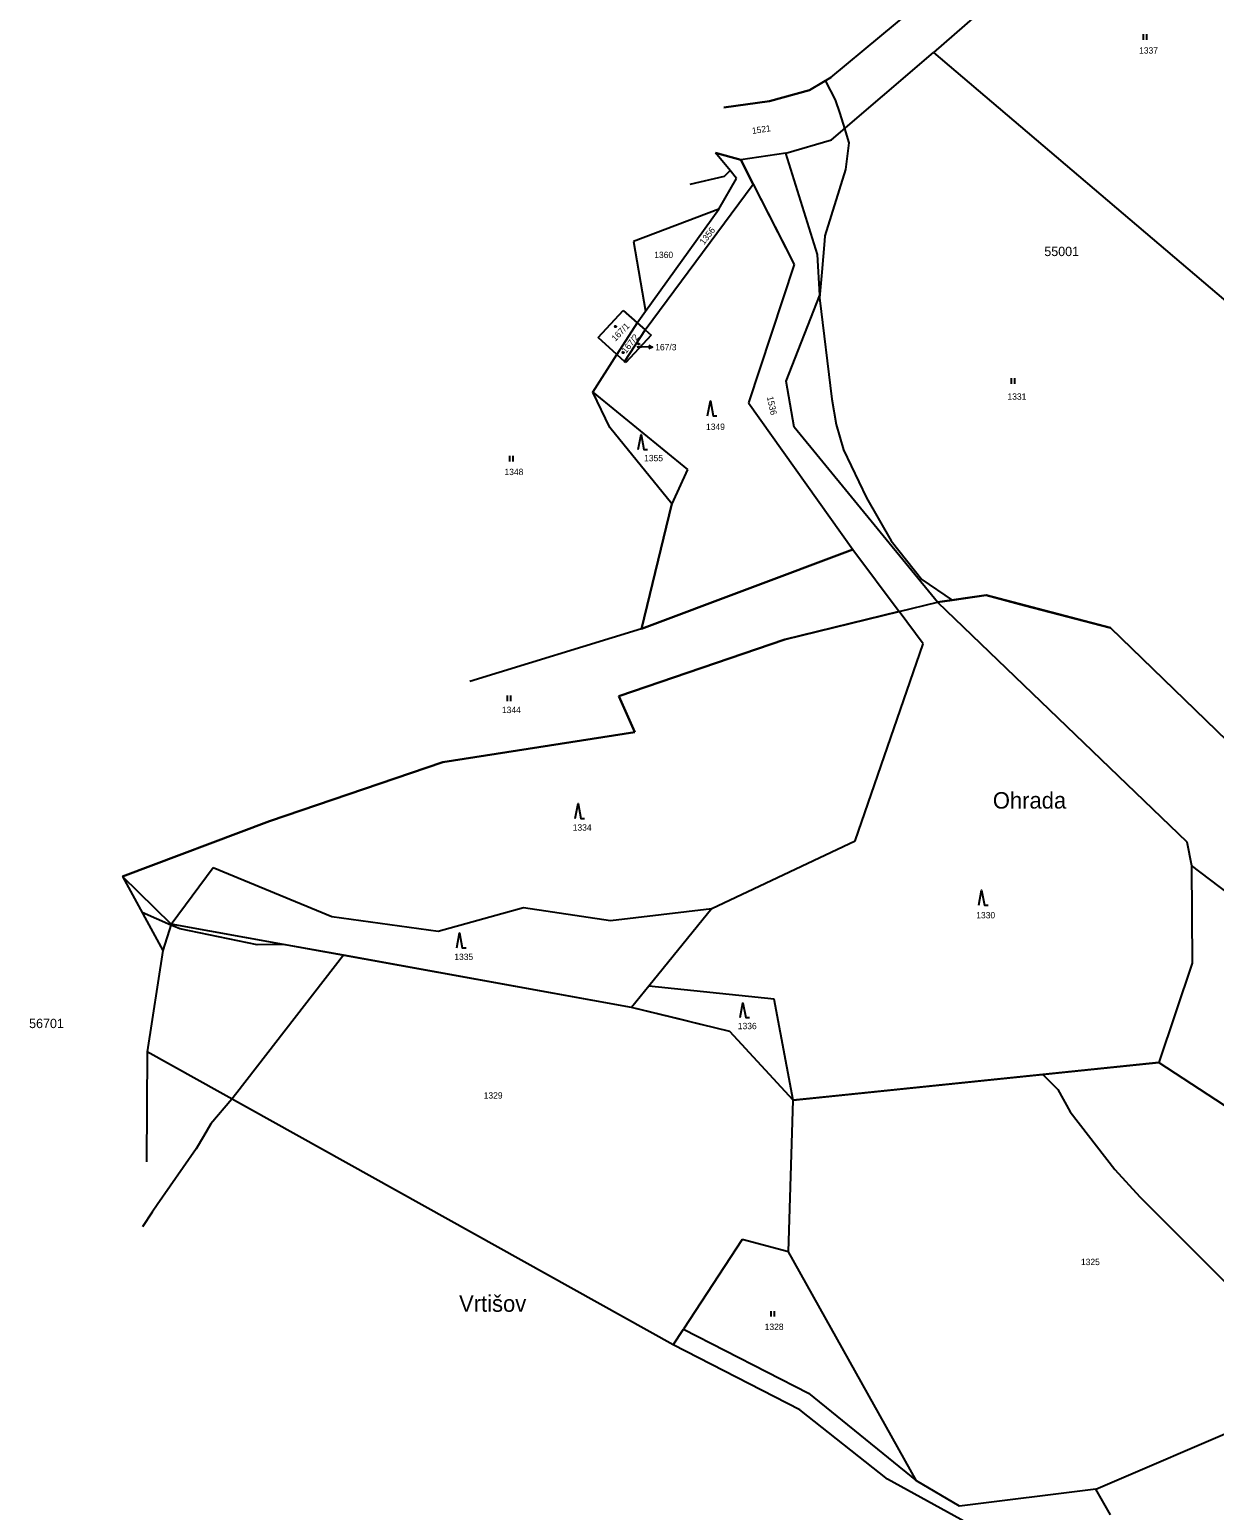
# Model space of a CAD drawing. Extents: x -792913 to -792113, y -1112764 to -1111548.
# Drawn here: x -792913.1 to -792595.9, y -1112340 to -1111943.5 of the extents above; entities that cross this region are included whole.
import ezdxf

# ---------------------------------------------------------------- set-up
doc = ezdxf.new("R2010")
doc.units = 0
for name, color, linetype in [('Vrstva 1', 7, 'Continuous'), ('Vrstva 11', 7, 'Continuous'), ('Vrstva 12', 7, 'Continuous'), ('Vrstva 2', 7, 'Continuous'), ('Vrstva 3', 7, 'Continuous'), ('Vrstva 5', 7, 'Continuous'), ('Vrstva 7', 7, 'Continuous')]:
    doc.layers.add(name, color=color, linetype=linetype)

msp = doc.modelspace()

# ---------------------------------------------------------------- linework, layer by layer
at = {"layer": 'Vrstva 1'}
for p, q in [((-792698.63, -1111956.28), (-792632.44, -1111901.27)), ((-792613.34, -1111899), (-792671.11, -1111949.58)), ((-792698.44, -1111972.97), (-792671.11, -1111949.58)), ((-792671.11, -1111949.58), (-792589.25, -1112019.19)), ((-792698.63, -1111956.28), (-792704.33, -1111959.64)), ((-792704.33, -1111959.64), (-792715.05, -1111962.61)), ((-792715.05, -1111962.61), (-792727.23, -1111964.35)), ((-792710.66, -1111976.53), (-792698.44, -1111972.97)), ((-792722.71, -1111978.37), (-792729.43, -1111976.43)), ((-792729.43, -1111976.43), (-792729.43, -1111976.43)), ((-792725.54, -1111981.2), (-792729.43, -1111976.43)), ((-792710.66, -1111976.53), (-792722.71, -1111978.37)), ((-792702.13, -1112003.67), (-792710.66, -1111976.53)), ((-792727.08, -1111982.75), (-792725.54, -1111981.2)), ((-792723.81, -1111983.32), (-792725.54, -1111981.2)), ((-792719.38, -1111984.88), (-792722.71, -1111978.37)), ((-792748.29, -1112023.9), (-792719.38, -1111984.88)), ((-792736.25, -1111984.83), (-792727.08, -1111982.75)), ((-792728.56, -1111991.52), (-792723.81, -1111983.32)), ((-792719.38, -1111984.88), (-792708.39, -1112006.35)), ((-792728.56, -1111991.52), (-792751.41, -1112000.24)), ((-792748.18, -1112018.91), (-792728.56, -1111991.52)), ((-792751.41, -1112000.24), (-792748.18, -1112018.91)), ((-792701.57, -1112014.57), (-792702.13, -1112003.67)), ((-792708.39, -1112006.35), (-792720.64, -1112043.39)), ((-792710.57, -1112037.62), (-792701.57, -1112014.57)), ((-792760.89, -1112025.9), (-792754.15, -1112018.68)), ((-792754.15, -1112018.68), (-792754.15, -1112018.68)), ((-792754.15, -1112018.68), (-792750.41, -1112022.02)), ((-792750.41, -1112022.02), (-792748.18, -1112018.91)), ((-792750.41, -1112022.02), (-792755.88, -1112030.47)), ((-792748.29, -1112023.9), (-792753.83, -1112032.34)), ((-792750.41, -1112022.02), (-792748.29, -1112023.9)), ((-792748.29, -1112023.9), (-792746.73, -1112025.29)), ((-792755.88, -1112030.47), (-792760.89, -1112025.9)), ((-792746.73, -1112025.29), (-792753.49, -1112032.65)), ((-792762.35, -1112040.52), (-792755.88, -1112030.47)), ((-792755.88, -1112030.47), (-792753.83, -1112032.34)), ((-792753.49, -1112032.65), (-792753.83, -1112032.34)), ((-792762.35, -1112040.52), (-792736.94, -1112061.27)), ((-792757.8, -1112049.99), (-792762.35, -1112040.52)), ((-792762.35, -1112040.52), (-792762.35, -1112040.52)), ((-792708.41, -1112049.93), (-792710.57, -1112037.62)), ((-792720.64, -1112043.39), (-792692.69, -1112082.72)), ((-792741.17, -1112070.46), (-792757.8, -1112049.99)), ((-792670.05, -1112096.82), (-792708.41, -1112049.93)), ((-792736.94, -1112061.27), (-792741.17, -1112070.46)), ((-792741.17, -1112070.46), (-792749.31, -1112103.9)), ((-792749.31, -1112103.9), (-792692.69, -1112082.72)), ((-792692.69, -1112082.72), (-792680.31, -1112099.32)), ((-792657.05, -1112094.97), (-792670.05, -1112096.82)), ((-792623.73, -1112103.69), (-792657.05, -1112094.97)), ((-792680.31, -1112099.32), (-792710.95, -1112106.79)), ((-792680.31, -1112099.32), (-792670.05, -1112096.82)), ((-792673.9, -1112107.92), (-792680.31, -1112099.32)), ((-792670.05, -1112096.82), (-792603.33, -1112161)), ((-792749.31, -1112103.9), (-792795.23, -1112118.08)), ((-792583.87, -1112142.36), (-792623.73, -1112103.69)), ((-792710.95, -1112106.79), (-792755.33, -1112121.94)), ((-792692.04, -1112160.72), (-792673.9, -1112107.92)), ((-792795.23, -1112118.08), (-792795.23, -1112118.08)), ((-792795.23, -1112118.08), (-792795.23, -1112118.08)), ((-792755.33, -1112121.94), (-792751.11, -1112131.6)), ((-792751.11, -1112131.6), (-792802.48, -1112139.62)), ((-792802.48, -1112139.62), (-792848.89, -1112155.49)), ((-792848.89, -1112155.49), (-792888.23, -1112170.24)), ((-792730.46, -1112178.86), (-792692.04, -1112160.72)), ((-792603.33, -1112161), (-792602.02, -1112167.3)), ((-792875.18, -1112183.03), (-792863.98, -1112167.89)), ((-792863.98, -1112167.89), (-792832.19, -1112181)), ((-792504.64, -1112241.47), (-792602.02, -1112167.3)), ((-792602.02, -1112167.3), (-792601.83, -1112193.48)), ((-792888.23, -1112170.24), (-792888.23, -1112170.24)), ((-792888.23, -1112170.24), (-792877.43, -1112190.06)), ((-792803.74, -1112184.93), (-792780.88, -1112178.61)), ((-792780.88, -1112178.61), (-792757.6, -1112182.07)), ((-792757.6, -1112182.07), (-792730.46, -1112178.86)), ((-792730.46, -1112178.86), (-792747.34, -1112199.64)), ((-792875.18, -1112183.03), (-792877.43, -1112190.06)), ((-792751.95, -1112205.32), (-792875.18, -1112183.03)), ((-792832.19, -1112181), (-792803.74, -1112184.93)), ((-792877.43, -1112190.06), (-792881.63, -1112217.24)), ((-792601.83, -1112193.48), (-792610.82, -1112220.07)), ((-792747.34, -1112199.64), (-792751.95, -1112205.32)), ((-792713.76, -1112203.08), (-792747.34, -1112199.64)), ((-792708.65, -1112230.19), (-792713.76, -1112203.08)), ((-792725.6, -1112211.79), (-792751.95, -1112205.32)), ((-792708.65, -1112230.19), (-792725.6, -1112211.79)), ((-792881.63, -1112217.24), (-792881.75, -1112246.69)), ((-792740.8, -1112295.69), (-792881.63, -1112217.24)), ((-792708.65, -1112230.19), (-792610.82, -1112220.07)), ((-792610.82, -1112220.07), (-792534.68, -1112269.92)), ((-792709.94, -1112270.78), (-792708.65, -1112230.19)), ((-792722.34, -1112267.5), (-792738.05, -1112291.49)), ((-792709.94, -1112270.78), (-792722.34, -1112267.5)), ((-792675.67, -1112332.12), (-792709.94, -1112270.78)), ((-792740.8, -1112295.69), (-792738.05, -1112291.49)), ((-792738.05, -1112291.49), (-792704.62, -1112308.67)), ((-792706.91, -1112313.12), (-792740.8, -1112295.69)), ((-792704.62, -1112308.67), (-792675.67, -1112332.12)), ((-792683.47, -1112331.71), (-792706.91, -1112313.12)), ((-792627.65, -1112334.38), (-792582.04, -1112314.76)), ((-792662.04, -1112343.48), (-792683.47, -1112331.71)), ((-792664.12, -1112338.86), (-792675.67, -1112332.12)), ((-792627.65, -1112334.38), (-792664.12, -1112338.86)), ((-792623.71, -1112341.2), (-792627.65, -1112334.38))]:
    msp.add_line(p, q, dxfattribs=at)
at = {"layer": 'Vrstva 11'}
for p, q in [((-792698.63, -1111956.28), (-792632.44, -1111901.27)), ((-792704.33, -1111959.64), (-792700.12, -1111957.16)), ((-792700.12, -1111957.16), (-792698.63, -1111956.28)), ((-792700.12, -1111957.16), (-792700.05, -1111957.28)), ((-792700.05, -1111957.28), (-792697.42, -1111962.27)), ((-792715.05, -1111962.61), (-792704.33, -1111959.64)), ((-792727.23, -1111964.35), (-792715.05, -1111962.61)), ((-792697.42, -1111962.27), (-792696.23, -1111965.97)), ((-792696.23, -1111965.97), (-792694.95, -1111969.98)), ((-792694.95, -1111969.98), (-792693.74, -1111973.75)), ((-792729.43, -1111976.43), (-792722.71, -1111978.37)), ((-792693.74, -1111973.75), (-792694.67, -1111980.93)), ((-792722.71, -1111978.37), (-792719.38, -1111984.88)), ((-792694.67, -1111980.93), (-792700.19, -1111998.72)), ((-792719.38, -1111984.88), (-792711.64, -1112000)), ((-792711.64, -1112000), (-792708.39, -1112006.35)), ((-792700.3, -1112000), (-792701.01, -1112008.42)), ((-792700.19, -1111998.72), (-792700.3, -1112000)), ((-792708.39, -1112006.35), (-792720.64, -1112043.39)), ((-792701.01, -1112008.42), (-792701.59, -1112015.27)), ((-792701.59, -1112015.27), (-792698.3, -1112042.41)), ((-792757.8, -1112049.99), (-792762.35, -1112040.52)), ((-792720.64, -1112043.39), (-792692.69, -1112082.72)), ((-792698.3, -1112042.41), (-792697.16, -1112049.21)), ((-792741.17, -1112070.46), (-792757.8, -1112049.99)), ((-792697.16, -1112049.21), (-792695.17, -1112056.02)), ((-792695.17, -1112056.02), (-792689.05, -1112068.84)), ((-792749.31, -1112103.9), (-792741.17, -1112070.46)), ((-792689.05, -1112068.84), (-792682.49, -1112080.4)), ((-792682.49, -1112080.4), (-792674.2, -1112090.73)), ((-792692.69, -1112082.72), (-792749.31, -1112103.9)), ((-792674.2, -1112090.73), (-792666.1, -1112096.26)), ((-792670.05, -1112096.82), (-792666.1, -1112096.26)), ((-792666.1, -1112096.26), (-792657.05, -1112094.97)), ((-792657.05, -1112094.97), (-792646.75, -1112097.66)), ((-792710.95, -1112106.79), (-792680.31, -1112099.32)), ((-792680.31, -1112099.32), (-792670.05, -1112096.82)), ((-792646.75, -1112097.66), (-792623.73, -1112103.69)), ((-792623.73, -1112103.69), (-792583.87, -1112142.36)), ((-792755.33, -1112121.94), (-792710.95, -1112106.79)), ((-792751.11, -1112131.6), (-792755.33, -1112121.94)), ((-792802.48, -1112139.62), (-792751.11, -1112131.6)), ((-792848.89, -1112155.49), (-792802.48, -1112139.62)), ((-792888.23, -1112170.24), (-792848.89, -1112155.49)), ((-792589.1, -1112177.14), (-792602.02, -1112167.3)), ((-792602.02, -1112167.3), (-792601.83, -1112193.48)), ((-792875.18, -1112183.03), (-792888.23, -1112170.24)), ((-792875.26, -1112183.27), (-792882.98, -1112179.87)), ((-792874.55, -1112183.58), (-792875.26, -1112183.27)), ((-792845.09, -1112188.48), (-792875.18, -1112183.03)), ((-792872.85, -1112184.33), (-792874.55, -1112183.58)), ((-792852.15, -1112188.56), (-792872.85, -1112184.33)), ((-792829.1, -1112191.37), (-792857.58, -1112228.22)), ((-792845.09, -1112188.48), (-792852.15, -1112188.56)), ((-792829.1, -1112191.37), (-792845.09, -1112188.48)), ((-792751.95, -1112205.32), (-792829.1, -1112191.37)), ((-792601.83, -1112193.48), (-792610.82, -1112220.07)), ((-792739, -1112208.5), (-792751.95, -1112205.32)), ((-792733.39, -1112209.87), (-792739, -1112208.5)), ((-792733.33, -1112209.89), (-792733.39, -1112209.87)), ((-792725.6, -1112211.79), (-792733.33, -1112209.89)), ((-792708.65, -1112230.19), (-792725.6, -1112211.79)), ((-792641.89, -1112223.28), (-792703.35, -1112229.64)), ((-792610.82, -1112220.07), (-792641.89, -1112223.28)), ((-792641.89, -1112223.28), (-792637.81, -1112227.3)), ((-792637.81, -1112227.3), (-792634.53, -1112233.29)), ((-792858.96, -1112229.87), (-792864.53, -1112236.54)), ((-792857.58, -1112228.22), (-792858.96, -1112229.87)), ((-792703.35, -1112229.64), (-792708.65, -1112230.19)), ((-792634.53, -1112233.29), (-792622.53, -1112248.77)), ((-792864.53, -1112236.54), (-792866.5, -1112239.88)), ((-792868.47, -1112243.23), (-792878.94, -1112258.24)), ((-792866.5, -1112239.88), (-792868.47, -1112243.23)), ((-792622.53, -1112248.77), (-792615.88, -1112256.1)), ((-792878.94, -1112258.24), (-792880.24, -1112260.17)), ((-792615.88, -1112256.1), (-792581.75, -1112290.24)), ((-792880.24, -1112260.17), (-792882.88, -1112264.08))]:
    msp.add_line(p, q, dxfattribs=at)
at = {"layer": 'Vrstva 12'}
for p, q in [((-792760.89, -1112025.9), (-792754.15, -1112018.68)), ((-792754.15, -1112018.68), (-792750.41, -1112022.02)), ((-792750.41, -1112022.02), (-792748.29, -1112023.9)), ((-792748.29, -1112023.9), (-792746.73, -1112025.29)), ((-792755.88, -1112030.47), (-792760.89, -1112025.9)), ((-792746.73, -1112025.29), (-792753.49, -1112032.65)), ((-792755.88, -1112030.47), (-792753.83, -1112032.34)), ((-792753.49, -1112032.65), (-792753.83, -1112032.34))]:
    msp.add_line(p, q, dxfattribs=at)
at = {"layer": 'Vrstva 3'}
for p, q in [((-792615, -1111944.73), (-792615, -1111946.23)), ((-792614, -1111946.23), (-792614, -1111944.73)), ((-792650.31, -1112036.83), (-792650.31, -1112038.33)), ((-792649.31, -1112038.33), (-792649.31, -1112036.83)), ((-792784.65, -1112057.62), (-792784.65, -1112059.12)), ((-792783.65, -1112059.12), (-792783.65, -1112057.62)), ((-792785.24, -1112121.81), (-792785.24, -1112123.31)), ((-792784.24, -1112123.31), (-792784.24, -1112121.81)), ((-792714.69, -1112286.64), (-792714.69, -1112288.14)), ((-792713.69, -1112288.14), (-792713.69, -1112286.64))]:
    msp.add_line(p, q, dxfattribs=at)
for points in [[(-792731.59, -1112046.89), (-792730.84, -1112042.89), (-792730.09, -1112046.89), (-792729.09, -1112046.89)], [(-792750.15, -1112055.88), (-792749.4, -1112051.88), (-792748.65, -1112055.88), (-792747.65, -1112055.88)], [(-792767.02, -1112154.73), (-792766.27, -1112150.73), (-792765.52, -1112154.73), (-792764.52, -1112154.73)], [(-792658.99, -1112177.92), (-792658.24, -1112173.92), (-792657.49, -1112177.92), (-792656.49, -1112177.92)], [(-792798.75, -1112189.35), (-792798, -1112185.35), (-792797.25, -1112189.35), (-792796.25, -1112189.35)], [(-792722.88, -1112208.06), (-792722.13, -1112204.06), (-792721.38, -1112208.06), (-792720.38, -1112208.06)]]:
    msp.add_lwpolyline(points, dxfattribs=at)
at = {"layer": 'Vrstva 5'}
for points in [[(-792756.11, -1112022.84), (-792756.02, -1112022.99), (-792756.11, -1112023.14), (-792756.29, -1112023.14), (-792756.38, -1112022.99), (-792756.29, -1112022.84)], [(-792749.89, -1112027.49), (-792749.8, -1112027.64), (-792749.89, -1112027.79), (-792750.07, -1112027.79), (-792750.16, -1112027.64), (-792750.07, -1112027.49)], [(-792754.09, -1112029.8), (-792754, -1112029.95), (-792754.09, -1112030.1), (-792754.27, -1112030.1), (-792754.36, -1112029.95), (-792754.27, -1112029.8)]]:
    msp.add_lwpolyline(points, close=True, dxfattribs=at)
at = {"layer": 'Vrstva 7'}
for p in [(-792750.47, -1112028.43), (-792746.32, -1112028.468)]:
    msp.add_line(p, (-792749.32, -1112028.44), dxfattribs=at)
msp.add_lwpolyline([(-792747.315, -1112027.959), (-792746.32, -1112028.468), (-792747.325, -1112028.959)], dxfattribs=at)

# ---------------------------------------------------------------- texts
at = {"layer": 'Vrstva 11'}
for s, p in [('55001', (-792641.452, -1112004.12)), ('56701', (-792913.215, -1112210.87))]:
    msp.add_text(s, height=2.5, dxfattribs=at).set_placement(p)
at = {"layer": 'Vrstva 2'}
for s, height, p in [('1337', 1.7, (-792616.077, -1111949.89)), ('1360', 1.7, (-792745.867, -1112004.65)), ('167/3', 0.1, (-792750.654, -1112028.43)), ('1331', 1.7, (-792651.307, -1112042.59)), ('1349', 1.7, (-792732.017, -1112050.67)), ('1355', 1.7, (-792748.587, -1112059.06)), ('1348', 1.7, (-792785.967, -1112062.77)), ('1344', 1.7, (-792786.647, -1112126.51)), ('1334', 1.7, (-792767.697, -1112157.99)), ('1330', 1.7, (-792659.667, -1112181.48)), ('1335', 1.7, (-792799.397, -1112192.63)), ('1336', 1.7, (-792723.507, -1112211.16)), ('1329', 1.7, (-792791.527, -1112229.75)), ('1325', 1.7, (-792631.637, -1112274.35)), ('1328', 1.7, (-792716.307, -1112291.71))]:
    msp.add_text(s, height=height, dxfattribs=at).set_placement(p)
for s, rotation, p in [('1521', 8.82355, (-792719.572, -1111971.44)), ('1356', 52.42564, (-792732.531, -1112001.199)), ('167/1', 45.77933, (-792756.301, -1112027.083)), ('167/2', 51.90998, (-792753.394, -1112030.334)), ('1536', 282.23901, (-792715.727, -1112041.864))]:
    msp.add_text(s, height=1.7, rotation=rotation, dxfattribs=at).set_placement(p)
at = {"layer": 'Vrstva 7'}
for s, height, p in [('167/3', 1.7, (-792745.612, -1112029.35)), ('Ohrada', 4.4, (-792655.224, -1112152.08)), ('Vrtišov', 4.4, (-792798.118, -1112286.84))]:
    msp.add_text(s, height=height, dxfattribs=at).set_placement(p)

doc.saveas('drawing.dxf')
